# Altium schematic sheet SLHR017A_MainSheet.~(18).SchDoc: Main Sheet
size 431 x 279 mm; Date: Not shown in title block; ApprovedBy: Not shown in title block; CheckedBy: Not shown in title block; Author: Not shown in title block; CompanyName: Not shown in title block; DrawnBy: Kirby Kruckmeyer; Engineer: Not shown in title block; Organization: Not shown in title block; Address1: Not shown in title block; Address2: Not shown in title block; Address3: Not shown in title block; Address4: Not shown in title block; DocumentNumber: 1; Revision: Use project parameter SCH_Rev; SheetNumber: 1; SheetTotal: 2; PageSetup: Record=PageOptions¦CenterHorizontal=True¦CenterVertical=True¦PrintScale=1.00¦XCorrection=1.00¦YCorrection=1.00¦PrintKind=0¦BorderSize=5000000¦LeftOffset=0¦BottomOffset=0¦Orientation=2¦PaperLength=1000¦PaperWidth=1000¦Scale=100¦PaperSource=15¦PrintQuality=600¦MediaType=1¦DitherType=10¦PaperKind=Letter¦PrintScaleMode=1
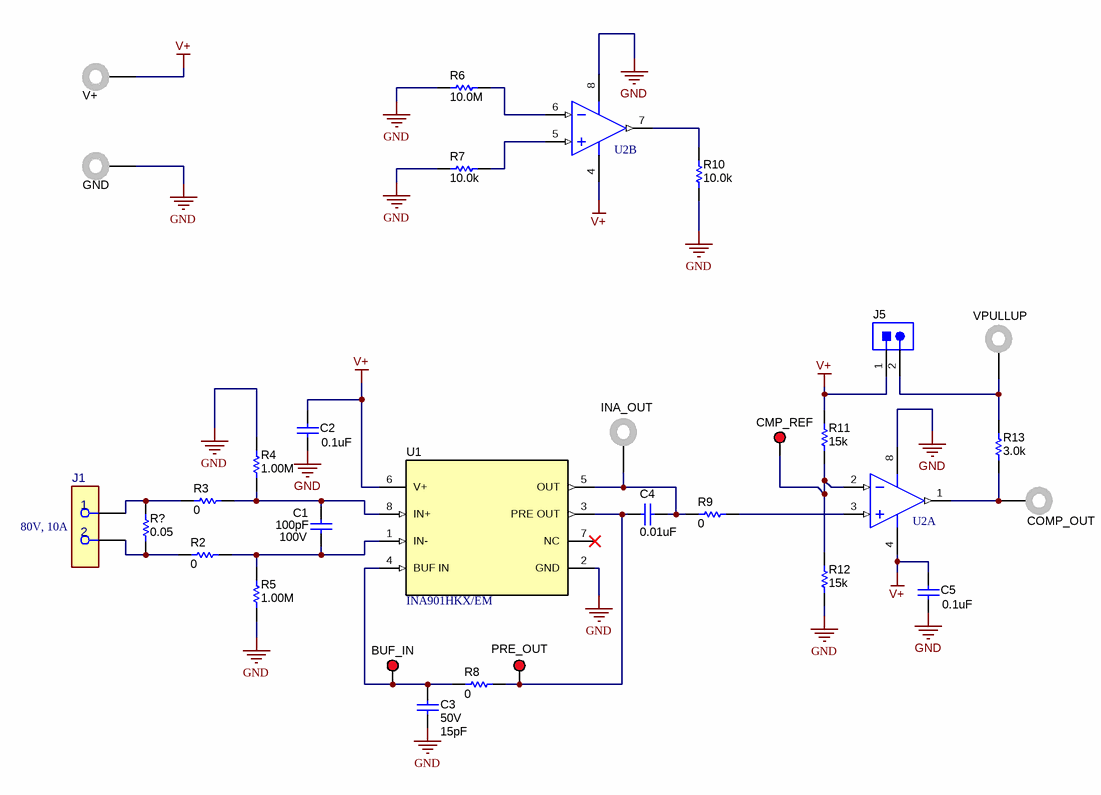
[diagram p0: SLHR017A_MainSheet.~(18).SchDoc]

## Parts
C1  Cap_F: 100pF  VDC_V: 100V  [0805_HV]  (hidden comment: C0805C101J1RACTU)
C2  ValueDisplayed: 0.1uF  [0805_HV]  (hidden comment: C0805C104K1RACTU)
C3  VDC_V: 50V  ValueDisplayed: 15pF  [0805_HV]  (hidden comment: VJ0805A150JXACW1BC)
C4  ValueDisplayed: 0.01uF  [0805_HV]  (hidden comment: C0805C103F1GACTU)
C5  ValueDisplayed: 0.1uF  [0805_HV]  (hidden comment: C0805C104K1RACTU)
J1  691137710002  [FP-691137710002_HDR2-MFG]  (value not drawn)
J2  V+  [Keystone_575-4]
J3  GND  [Keystone_575-4]
J4  INA_OUT  [Keystone_575-4]
J5  PBC02SAAN  [Sullins_PBC02SAAN]  (value not drawn)
J6  VPULLUP  [Keystone_575-4]
J7  COMP_OUT  [Keystone_575-4]
R2  ValueDisplayed: 0  [0805_HV]  (hidden comment: ERJ-6GEY0R00V)
R3  ValueDisplayed: 0  [0805_HV]  (hidden comment: ERJ-6GEY0R00V)
R4  ValueDisplayed: 1.00M  [0805_HV]  (hidden comment: CRCW08051M00FKEA)
R5  ValueDisplayed: 1.00M  [0805_HV]  (hidden comment: CRCW08051M00FKEA)
R6  ValueDisplayed: 10.0M  [0805_HV]  (hidden comment: CRCW080510M0FKEA)
R7  ValueDisplayed: 10.0k  [0805_HV]  (hidden comment: RNCP0805FTD10K0)
R8  ValueDisplayed: 0  [0805_HV]  (hidden comment: ERJ-6GEY0R00V)
R9  ValueDisplayed: 0  [0805_HV]  (hidden comment: ERJ-6GEY0R00V)
R10  ValueDisplayed: 10.0k  [0805_HV]  (hidden comment: RNCP0805FTD10K0)
R11  ValueDisplayed: 15k  [0805_HV]  (hidden comment: ERJ-6GEYJ153V)
R12  ValueDisplayed: 15k  [0805_HV]  (hidden comment: ERJ-6GEYJ153V)
R13  ValueDisplayed: 3.0k  [0805_HV]  (hidden comment: ERJ-6GEYJ302V)
R?  ValueDisplayed: 0.05  [3518_WIDE]  (hidden comment: FCSL90R050FER)
TP1  BUF_IN  [Keystone5010]
TP2  PRE_OUT  [Keystone5010]
TP3  CMP_REF  [Keystone5010]
U1  INA901HKX/EM  [HKX0008A_Custom_B]
U2  LM193AJRLQMLV  [NAB0008A]  (value not drawn)  (parts A,B of 2)

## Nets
GND: C2.2 C3.2 C5.2 J3.1 R4.2 R5.1 R6.1 R7.1 R10.1 R12.1 U1.2(GND) U2.8(V+)
V+: C2.1 C5.1 J2.1 J5.1 R11.2 U1.6(V+) U2.4(GND)
NetC1_1: C1.1 R3.2 R4.1 U1.8(IN+)
NetC1_2: C1.2 R2.2 R5.2 U1.1(IN-)
NetC3_1: C3.1 R8.1 TP1.1 U1.4(BUF_IN)
NetC4_1: C4.1 R8.2 TP2.1 U1.3(PRE_OUT)
NetC4_2: C4.2 J4.1 R9.1 U1.5(OUT)
NetJ1_1: J1.1 R3.1 R?.2
NetJ1_2: J1.2 R2.1 R?.1
NetJ5_2: J5.2 J6.1 R13.2
NetJ7_1: J7.1 R13.1 U2.1(OUTA)
NetR6_2: R6.2 U2.6(INB-)
NetR7_2: R7.2 U2.5(INB+)
NetR9_2: R9.2 U2.3(INA+)
NetR10_2: R10.2 U2.7(OUTB)
NetR11_1: R11.1 R12.2 TP3.1 U2.2(INA-)

Not connected (* = marked no-connect by the designer): U1 7(NC)*

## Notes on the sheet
- (near J1) 80V, 10A

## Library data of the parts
C1 = CMP-0007706-2: CAP, CERM, 100 pF, 100 V, +/- 5%, X7R, 0805; Manufacturer: Kemet; TaMin_C: -55°C; Polarized: N; SizeAreaWB_mm2: 6.75; Value1: Unknown; U/M: EA; Value: 100pF; TaMax_C: 125°C; SizeZ_mm: 1.45; SizeX_mm: 2; SizeY_mm: 1.25; Cap_Case: 0805; SizeArea_mm2: 2.5; AEC Category: Q200
C2 C5 = CMP-0007722-2: CAP, CERM, 0.1 uF, 100 V, +/- 10%, X7R, 0805; Manufacturer: Kemet; TaMin_C: -55°C; ESR_ohm: 0.064; Polarized: N; SizeAreaWB_mm2: 6.75; Value1: 0.064 ohm; U/M: EA; Value: 0.1uF; TaMax_C: 125°C; SizeZ_mm: 1.45; SizeX_mm: 2; SizeY_mm: 1.25; Cap_Case: 0805; Value2: 100V; SizeArea_mm2: 2.5; Cap_F: 100nF; IRMS_A: 1.64A; AEC Category: Q200
C3 = CMP-0008431-2: CAP, CERM, 15 pF, 50 V, +/- 5%, C0G/NP0, 0805; Manufacturer: Vishay-Bccomponents; TaMin_C: -55°C; Polarized: N; SizeAreaWB_mm2: 6.75; Value1: Unknown; U/M: EA; Value: 15pF; TaMax_C: 125°C; SizeZ_mm: 1.45; SizeX_mm: 2; SizeY_mm: 1.25; Cap_Case: 0805; SizeArea_mm2: 2.5; AEC Category: Q200
C4 = CMP-0007716-2: CAP, CERM, 0.01 uF, 100 V, +/- 1%, C0G/NP0, 0805; Manufacturer: Kemet; TaMin_C: -55°C; Polarized: N; SizeAreaWB_mm2: 6.75; Value1: Unknown; U/M: EA; Value: 0.01uF; TaMax_C: 125°C; SizeZ_mm: 1.45; SizeX_mm: 2; SizeY_mm: 1.25; Cap_Case: 0805; Value2: 100V; SizeArea_mm2: 2.5; Cap_F: 10nF; AEC Category: Q200
J1 = CMP-0087503-1: TERM BLK 2POS SIDE ENTRY 5MM PCB; Manufacturer: Würth Elektronik; Symbol Name: SYM-691137710002; Row_Count: 1; Current_A: 16A; ContactFinish: Tin,Nickel; Voltage_V: 300V
J2-J4 J6 J7 = CMP-0055165-2: Standard Banana Jack, Uninsulated, 5.5mm; Manufacturer: Keystone; PartNumber: 575-4; CT: TRUE; Green_REACh: Passed; CNHeader: FALSE; Green_Lifecycle: Active
J5 = CMP-0054566-1: Header, 100mil, 2x1, Gold, TH; Manufacturer: Sullins Connector Solutions; CNHeader: TRUE; Current_A: 3A; Green_Lifecycle: Active; Shrouded: N; Gender: Male; Green_REACh: Passed; Voltage_V: 1.8kV; Row_Count: 1; Pitch_mm: 2.54; CT: FALSE; Cert_UL: Y
R2 R3 R8 R9 = CMP-0020616-3: RES, 0, 5%, 0.125 W, AEC-Q200 Grade 0, 0805; Manufacturer: Panasonic; Power_W: 125mW; TempCo: 600 ppm/C; Value_Code: 0000; Value: 0; EIA_Code: E24; SizeX_mm: 2; SizeY_mm: 1.25; SizeZ_mm: 1.45; Value2: 0.125W; SizeArea_mm2: 2.5; AEC Qualified: Y; VDC_V: 150V; AEC Category: Q200; SizeAreaWB_mm2: 6.75
R4 R5 = CMP-0020980-3: RES, 1.00 M, 1%, 0.125 W, AEC-Q200 Grade 0, 0805; Manufacturer: Vishay-Dale; Power_W: 125mW; TempCo: 100 ppm/C; Value_Code: 1M00; Value: 1.00Meg; EIA_Code: E96; Res_ohm: 1M; SizeX_mm: 2; SizeY_mm: 1.25; SizeZ_mm: 1.45; Value2: 0.125W; AEC Qualified: Y; VDC_V: 150V; AEC Category: Q200; SizeArea_mm2: 2.5; AEC Grade: 0
R6 = CMP-0020846-3: RES, 10.0 M, 1%, 0.125 W, AEC-Q200 Grade 0, 0805; Manufacturer: Vishay-Dale; Power_W: 125mW; TempCo: 100 ppm/C; Value_Code: 10M0; Value: 10.0Meg; EIA_Code: E96; Res_ohm: 10M; SizeX_mm: 2; SizeY_mm: 1.25; SizeZ_mm: 1.45; Value2: 0.125W; SizeArea_mm2: 2.5; AEC Qualified: Y; VDC_V: 150V; AEC Category: Q200; AEC Grade: 0
R7 R10 = CMP-0084247-1: RES, 10.0 k, 1%, 0.25 W, AEC-Q200 Grade 0, 0805; Manufacturer: Stackpole Electronics Inc; Power_W: 250mW; Green_Lifecycle: Active; TempCo: 100 ppm/C; SizeAreaWB_mm2: 6.75; Value_Code: 10k0; Green_REACh: Passed; Value: 10.0k; EIA_Code: E96; Res_ohm: 10k; SizeX_mm: 2; SizeY_mm: 1.25; SizeZ_mm: 1.45; Value2: 0.25W; SizeArea_mm2: 2.5; AEC Qualified: Y; AEC Grade: 0; AEC Category: Q200
R11 R12 = CMP-0020646-3: RES, 15 k, 5%, 0.125 W, AEC-Q200 Grade 0, 0805; Manufacturer: Panasonic; Power_W: 125mW; TempCo: 200 ppm/C; Value_Code: 15k0; Value: 15k; EIA_Code: E24; SizeX_mm: 2; SizeY_mm: 1.25; SizeZ_mm: 1.45; Value2: 0.125W; SizeArea_mm2: 2.5; AEC Qualified: Y; VDC_V: 150V; AEC Category: Q200; AEC Grade: 0; SizeAreaWB_mm2: 6.75
R13 = CMP-0020698-3: RES, 3.0 k, 5%, 0.125 W, AEC-Q200 Grade 0, 0805; Manufacturer: Panasonic; Power_W: 125mW; TempCo: 200 ppm/C; Value_Code: 3k00; Value: 3.0k; EIA_Code: E24; Res_ohm: 3k; SizeX_mm: 2; SizeY_mm: 1.25; SizeZ_mm: 1.45; Value2: 0.125W; SizeArea_mm2: 2.5; AEC Qualified: Y; VDC_V: 150V; AEC Category: Q200; AEC Grade: 0; SizeAreaWB_mm2: 6.75
R? = CMP-0015082-2: RES, 0.05, 1%, 4 W, 3518 WIDE; Manufacturer: Ohmite; Power_W: 4W; TempCo: 50 ppm/C; SizeAreaWB_mm2: 79.52; Value_Code: R050; U/M: EA; Value: 0.05; EIA_Code: E96; SizeX_mm: 9.2; SizeY_mm: 5.1; SizeZ_mm: 0.7; SizeArea_mm2: 46.92; VDC_V: 0V; AEC Category: Q200
TP1-TP3 = CMP-0055147-1: Test Point, Multipurpose, Red, TH; Manufacturer: Keystone; PartNumber: 5010; CNHeader: FALSE; Green_Lifecycle: Active; Green_REACh: Passed; ContactFinish: Silver; CT: TRUE
U1 = CMP-0081563-2: Voltage Output, Unidirectional Measurement Current-Shunt Monitor, HKX0008A (CFP-8); Manufacturer: Texas Instruments; SizeZ_mm: 2.8; Rating: Space; AEC Category: Q200; CompType: IC; AEC Qualified: N
U2 = CMP-0067897-1: Low Power Low Offset Voltage Dual Comparator, 8-pin CerDIP; Manufacturer: Texas Instruments; High-Reliability: Y; CompType: Amplifiers; PackageTopMarking: NSZSSXXYYA*LM193AJRLV Q*5962R*9452603VPA; PowerWise: N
